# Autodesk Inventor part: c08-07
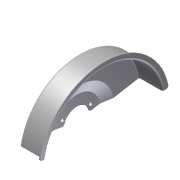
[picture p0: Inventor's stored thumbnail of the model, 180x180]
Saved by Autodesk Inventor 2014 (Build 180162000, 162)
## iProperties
Created: 2010-12
Part Number: c08-07
Material: Steel
Document SubType Name: Sheet Metal
Designer: Thom Tremblay
Density: 7.85 g/cm^3
Sheet Metal Rule: 16ga Steel
Sheet Metal Width: 0.000 mm
Sheet Metal Length: 0.000 mm
Sheet Metal Area: 0.000 mm^2
Appearance: Steel
Author: Thom Tremblay
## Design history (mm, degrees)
sketch "Sketch1"
  geometry: L1 (0, 0)-(52.833, 0); L2 (0, 18)-(0, 32.5); L3 (0, 32.5)-(5, 46.237); L4 (5, 46.237)-(5, 82.5); L5 (5, 82.5)-(38, 82.5); L6 (38, 82.5)-(38, 90.5)
  constraints: 12 end point, 2 parallel, 2 perpendicular, 1 horizontal, 1 point on line
  dimensions: "d0" = 165 diameter of L5 L1; "d1" = 33 distance of L4.end L5.end; "d3" = 36 diameter of L2.start L1; "d4" = 65 diameter of L2.end L1; "d6" = 38 distance between parallel lines of L6 L2 (derived); "d23" = 5 horizontal distance of L2.end L3.end; "d24" = 20 deg angle of L2 L3; "d25" = 8 distance of L5.end L6.end
feature "Contour Roll1" sketch "Sketch1" dims "d9" = 160 deg, "d10" = 175.23857, "d11" = 62.75269, "Thickness" = 1.524 (derived)
sketch "Sketch2"
  geometry: L1 (0, 0)-(-19.486, 11.25); L2 (19.486, 11.25)-(0, 0); L3 (0, 0)-(0, 22.5); A1 r 22.5 centre (0, 0) between (19.486, 11.25) and (-19.486, 11.25)
  constraints: 6 end point, 3 point on circle, 1 centre point, 1 vertical
  dimensions: "d12" = 22.5 radius of A1; "d13" = 120 deg angle of L1 L2; "d14" = 60 deg angle of L1 L3 (= 0.5 x d13)
hole "Hole1" sketch "Sketch2" at (-19.486, 11.25), (19.486, 11.25) diameter "d15" = 4.4958; stored, may be unused: countersink angle "d19" = 82 deg, drill point angle "d21" = 118 deg; dims "d16" = 19.05, "d17" = 8.4328, "d18" = 6.35, "d20" = 1.524 (= Thickness)
feature "Corner Round1" dims "d22" = 2.54
body "Solid1"
other parameters: "BendRadius" = 1.524 (= Thickness), "BendReliefWidth" = 1.524 (= Thickness), "BendReliefDepth" = 0.762 (= 0.5 x Thickness), "CornerReliefSize" = 6.096 (= 4 x Thickness), "SeamGap" = 0.00508, "MinimumRemnant" = 3.048 (= 2 x Thickness), "TransitionRadius" = 1.524 (= BendRadius), "JacobiRadiusSize" = 1.524 (= BendRadius), "GapSize" = 1.524 (= Thickness), "d8" = 1.524 (= BendRadius)
